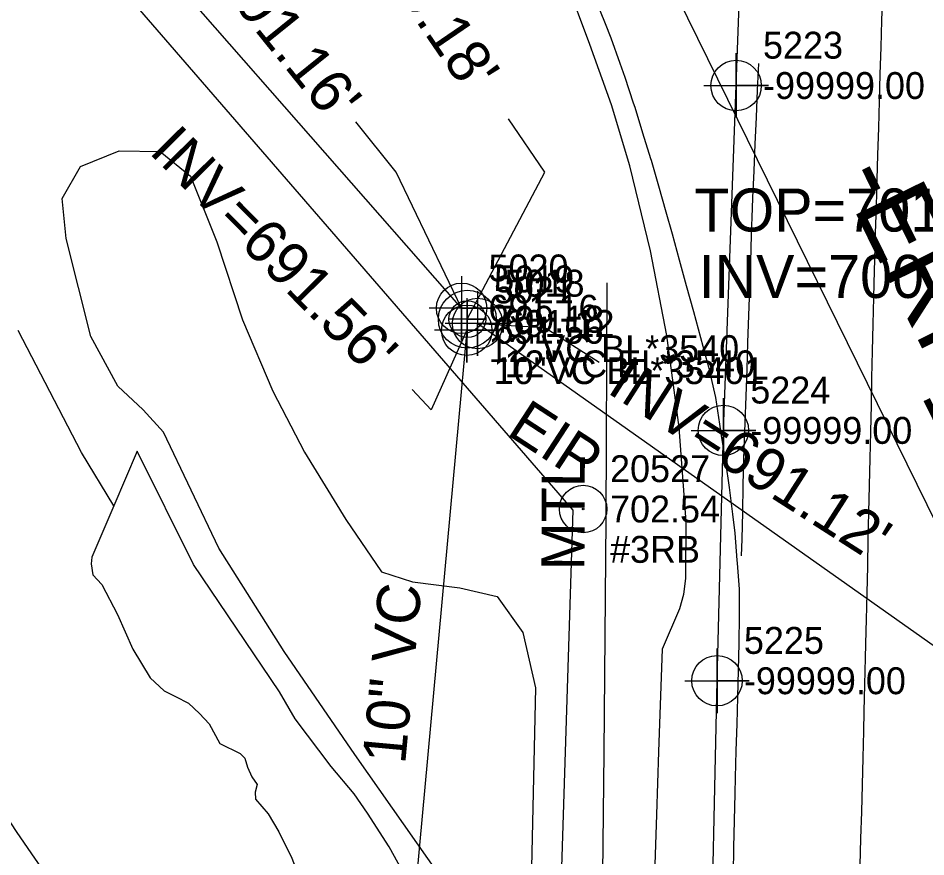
# Model space of a CAD drawing. Extents: x 1516784 to 1522736, y 634838 to 639369.
# Drawn here: x 1520350.8 to 1520435.2, y 637801.1 to 637879 of the extents above; entities that cross this region are included whole.
import ezdxf

# ---------------------------------------------------------------- set-up
doc = ezdxf.new("R2010")
doc.units = 0
for name, color, linetype in [('COGO Default Point Elevation', 7, 'Continuous'), ('COGO Default Point Number', 7, 'Continuous'), ('Exist Environmental Wetland Boundary Cogo Number', 7, 'Continuous'), ('Exist Environmental Wetland Boundary Text', 7, 'Continuous'), ('Exist Guardrail', 7, 'Continuous'), ('Exist Guardrail Text', 7, 'Continuous'), ('Exist Horizontal Alignment Direction Label', 7, 'Continuous'), ('Exist Hydro Stream or Body of Water', 7, 'Continuous'), ('Exist Hydro Stream or Body of Water Text', 7, 'Continuous'), ('Exist Property Iron Pin CELL', 7, 'Continuous'), ('Exist Property Iron Pin Cogo Comment', 7, 'Continuous'), ('Exist Property Iron Pin Cogo Elevation', 7, 'Continuous'), ('Exist Property Iron Pin Cogo Number', 7, 'Continuous'), ('Exist Property Iron Pin Text', 7, 'Continuous'), ('Exist Right of Way Line', 7, 'Continuous'), ('Exist Structure Minor Drop Inlet Top Elevation', 7, 'Continuous'), ('Exist Structure Minor Pipes RCP 18 Inch Invert', 7, 'Continuous'), ('Exist Utilities Gas UG Line SUE LOS B', 7, 'Continuous'), ('Exist Utilities Gas UG Line SUE LOS B Cogo Elevation', 7, 'Continuous'), ('Exist Utilities Gas UG Line SUE LOS B Cogo Number', 7, 'Continuous'), ('Exist Utilities Gas UG Line SUE LOS B Cogo Point CELL', 7, 'Continuous'), ('Exist Utilities Sanitary Sewer Manhole CELL', 7, 'Continuous'), ('Exist Utilities Sanitary Sewer Manhole Cogo Elevation', 7, 'Continuous'), ('Exist Utilities Sanitary Sewer Manhole Cogo Number', 7, 'Continuous'), ('Exist Utilities Sanitary Sewer Manhole Leader', 7, 'Continuous'), ('Exist Utilities Sanitary Sewer Manhole Text', 7, 'Continuous'), ('Exist Utilities Sanitary Sewer UG Line', 7, 'Continuous'), ('Exist Utilities Sanitary Sewer UG Line Cogo Comment', 7, 'Continuous'), ('Exist Utilities Sanitary Sewer UG Line Cogo Elevation', 7, 'Continuous'), ('Exist Utilities Sanitary Sewer UG Line Cogo Number', 7, 'Continuous'), ('Exist Utilities Sanitary Sewer UG Line Cogo Point CELL', 7, 'Continuous'), ('Exist Utilities Sanitary Sewer UG Line Invert Elevation', 7, 'Continuous'), ('Exist Utilities Sanitary Sewer UG Line Leader', 7, 'Continuous'), ('Exist Utilities Sanitary Sewer UG Line Text', 7, 'Continuous'), ('Exist Vegetation Hedge Row', 7, 'Continuous'), ('Scratch_Level_5', 7, 'Continuous')]:
    doc.layers.add(name, color=color, linetype=linetype)

msp = doc.modelspace()

# ---------------------------------------------------------------- linework, layer by layer
at = {"layer": 'COGO Default Point Elevation'}
for points in [[(1520431.184, 637881.303), (1520431.109, 637878.805), (1520431.035, 637876.306), (1520430.961, 637873.808), (1520430.887, 637871.309), (1520430.813, 637868.811), (1520430.739, 637866.312), (1520430.672, 637864.028), (1520430.595, 637861.53), (1520430.519, 637859.031), (1520430.443, 637856.533), (1520430.414, 637855.562), (1520430.357, 637853.063), (1520430.3, 637850.564), (1520430.243, 637848.064), (1520430.186, 637845.565), (1520430.129, 637843.066), (1520430.072, 637840.567), (1520430.015, 637838.068), (1520429.958, 637835.569), (1520429.901, 637833.07), (1520429.844, 637830.571), (1520429.787, 637828.072), (1520429.73, 637825.573), (1520429.673, 637823.074), (1520429.65, 637822.065), (1520429.591, 637819.566), (1520429.533, 637817.067), (1520429.475, 637814.568), (1520429.432, 637812.743), (1520429.364, 637810.244), (1520429.296, 637807.745), (1520429.228, 637805.246), (1520429.16, 637802.747), (1520429.092, 637800.248)], [(1520404.501, 637880.849), (1520405.413, 637878.522), (1520405.941, 637877.176), (1520406.783, 637874.823), (1520407.247, 637873.527), (1520408.033, 637871.154), (1520408.167, 637870.749), (1520408.899, 637868.358), (1520409.63, 637865.968), (1520409.676, 637865.819), (1520410.365, 637863.415), (1520411.055, 637861.012), (1520411.64, 637858.972), (1520412.299, 637856.56), (1520412.959, 637854.149), (1520413.614, 637851.753), (1520414.27, 637849.34), (1520414.926, 637846.928), (1520415.015, 637846.598), (1520415.567, 637844.16), (1520415.658, 637843.755), (1520416.042, 637841.284), (1520416.209, 637840.204), (1520416.59, 637837.733), (1520416.95, 637835.394), (1520417.256, 637832.913), (1520417.476, 637831.129), (1520417.658, 637828.636), (1520417.679, 637828.347), (1520417.875, 637825.949), (1520417.857, 637823.45), (1520417.838, 637820.905), (1520417.772, 637818.406), (1520417.706, 637815.907), (1520417.639, 637813.408), (1520417.573, 637810.91), (1520417.507, 637808.411), (1520417.467, 637806.925), (1520417.412, 637804.426), (1520417.356, 637801.927), (1520417.3, 637799.428)], [(1520419.664, 637874.807), (1520419.556, 637872.31), (1520419.448, 637869.813), (1520419.34, 637867.315), (1520419.233, 637864.818), (1520419.125, 637862.321), (1520419.083, 637861.367), (1520418.998, 637858.869), (1520418.912, 637856.371), (1520418.827, 637853.873), (1520418.741, 637851.375), (1520418.656, 637848.877), (1520418.57, 637846.379), (1520418.484, 637843.88), (1520418.399, 637841.382), (1520418.313, 637838.884), (1520418.286, 637838.083), (1520418.227, 637835.584), (1520418.168, 637833.085), (1520418.109, 637830.586), (1520418.072, 637829.028)]]:
    msp.add_lwpolyline(points, dxfattribs=at)
at = {"layer": 'COGO Default Point Number'}
msp.add_lwpolyline([(1520409.988, 637798.457), (1520410.203, 637804.975), (1520410.391, 637810.804), (1520410.757, 637820.381), (1520412.342, 637824.124), (1520412.722, 637825.48), (1520412.927, 637826.934), (1520412.951, 637832.187), (1520412.3, 637840.957), (1520411.153, 637849.529), (1520409.622, 637857.384), (1520407.698, 637865.279), (1520405.994, 637870.956), (1520403.976, 637876.57), (1520401.805, 637882.501)], dxfattribs=at)
at = {"layer": 'Exist Environmental Wetland Boundary Cogo Number'}
msp.add_lwpolyline([(1520361.047, 637788.842), (1520355.345, 637796.638), (1520350.769, 637803.307), (1520345.377, 637811.482), (1520336.329, 637825.407), (1520331.638, 637833.125), (1520326.352, 637842.523), (1520320.418, 637853.216), (1520316.843, 637859.318), (1520316.247, 637859.778)], dxfattribs=at)
at = {"layer": 'Exist Environmental Wetland Boundary Text'}
msp.add_line((1520409.906, 637885.524), (1520453.231, 637797.305), dxfattribs=at)
at = {"layer": 'Exist Guardrail'}
msp.add_lwpolyline([(1520404.156, 637757.609), (1520405.039, 637785.361), (1520405.323, 637810.742), (1520405.506, 637832.426), (1520405.596, 637854.408)], dxfattribs=at)
at = {"layer": 'Exist Hydro Stream or Body of Water'}
msp.add_lwpolyline([(1520359.729, 637833.671), (1520356.751, 637838.641), (1520350.849, 637849.968)], dxfattribs=at)
at = {"layer": 'Exist Hydro Stream or Body of Water Text'}
for p, q in [((1520361.914, 637838.752), (1520359.729, 637833.671)), ((1520367.135, 637828.24), (1520361.914, 637838.752)), ((1520359.729, 637833.671), (1520357.686, 637828.92)), ((1520375.151, 637816.378), (1520367.135, 637828.24))]:
    msp.add_line(p, q, dxfattribs=at)
for points in [[(1520357.686, 637828.92), (1520357.63, 637828.285), (1520357.783, 637827.28), (1520358.618, 637826.377), (1520360.077, 637823.571)], [(1520360.077, 637823.571), (1520361.506, 637820.352), (1520363.121, 637817.694), (1520364.422, 637816.483), (1520365.462, 637815.957), (1520366.692, 637815.343), (1520367.698, 637814.391), (1520368.602, 637813.425), (1520369.599, 637811.587)], [(1520379.952, 637809.439), (1520376.611, 637813.89), (1520375.151, 637816.378)], [(1520369.599, 637811.587), (1520371.491, 637810.658), (1520371.934, 637810.232), (1520372.162, 637809.379), (1520372.565, 637808.499), (1520373.06, 637807.783), (1520372.871, 637807.065), (1520372.924, 637806.422), (1520374.098, 637805.035)], [(1520386.859, 637799.224), (1520385.34, 637801.982), (1520383.33, 637805.123), (1520382.095, 637806.904), (1520379.952, 637809.439)], [(1520374.098, 637805.035), (1520375.079, 637803.374), (1520376.279, 637800.914), (1520376.856, 637799.477), (1520377.422, 637798.055), (1520378.262, 637796.413), (1520379.186, 637794.88), (1520379.229, 637794.806)]]:
    msp.add_lwpolyline(points, dxfattribs=at)
at = {"layer": 'Exist Property Iron Pin CELL'}
for radius in [2.203, 0.0707]:
    msp.add_circle((1520403.367, 637833.385), radius, dxfattribs=at)
at = {"layer": 'Exist Right of Way Line'}
for p, q in [((1520000.914, 638297.346), (1520402.397, 637833.275)), ((1520402.397, 637833.275), (1520393.319, 637546.213))]:
    msp.add_line(p, q, dxfattribs=at)
at = {"layer": 'Exist Utilities Gas UG Line SUE LOS B'}
msp.add_lwpolyline([(1520401.122, 637354.382), (1520402.422, 637385.791), (1520403.856, 637416.359), (1520404.692, 637446.503), (1520405.047, 637477.267), (1520405.743, 637508.887), (1520406.802, 637539.368), (1520408.241, 637570.499), (1520409.319, 637603.291), (1520409.994, 637633.11), (1520411.515, 637665.368), (1520412.117, 637695.323), (1520413.141, 637725.205), (1520414.219, 637755.916), (1520415.162, 637787.588), (1520415.812, 637817.42), (1520416.407, 637840.693), (1520417.587, 637872.753), (1520418.237, 637890.364), (1520419.072, 637920.653), (1520420.174, 637951.413), (1520420.842, 637982.369), (1520421.988, 638012.853), (1520423.241, 638041.594)], dxfattribs=at)
at = {"layer": 'Exist Utilities Gas UG Line SUE LOS B Cogo Point CELL'}
for points in [[(1520414.587, 637872.753), (1520420.587, 637872.753), (1520417.587, 637872.753), (1520417.587, 637875.753), (1520417.587, 637869.753)], [(1520413.407, 637840.693), (1520419.407, 637840.693), (1520416.407, 637840.693), (1520416.407, 637843.693), (1520416.407, 637837.693)], [(1520412.812, 637817.42), (1520418.812, 637817.42), (1520415.812, 637817.42), (1520415.812, 637820.42), (1520415.812, 637814.42)]]:
    msp.add_lwpolyline(points, dxfattribs=at)
for centre in [(1520417.587, 637872.753), (1520416.407, 637840.693), (1520415.812, 637817.42)]:
    msp.add_circle(centre, 2.344, dxfattribs=at)
at = {"layer": 'Exist Utilities Sanitary Sewer Manhole CELL'}
msp.add_lwpolyline([(1520392.601, 637852.74), (1520392.601, 637849.315), (1520392.601, 637851.028), (1520394.313, 637851.028), (1520390.889, 637851.028)], dxfattribs=at)
for radius in [2.694, 1.712]:
    msp.add_circle((1520392.601, 637851.028), radius, dxfattribs=at)
at = {"layer": 'Exist Utilities Sanitary Sewer Manhole Leader'}
msp.add_lwpolyline([(1520392.601, 637851.028), (1520399.815, 637864.688), (1520396.43, 637869.642)], dxfattribs=at)
at = {"layer": 'Exist Utilities Sanitary Sewer UG Line'}
for p, q in [((1520392.069, 637852.044), (1520196.281, 638075.269)), ((1520529.65, 637754.364), (1520393.555, 637850.627)), ((1520392.551, 637850.001), (1520383.58, 637752.527))]:
    msp.add_line(p, q, dxfattribs=at)
at = {"layer": 'Exist Utilities Sanitary Sewer UG Line Cogo Point CELL'}
for points in [[(1520392.069, 637855.044), (1520392.069, 637849.044), (1520392.069, 637852.044), (1520395.069, 637852.044), (1520389.069, 637852.044)], [(1520393.555, 637853.627), (1520393.555, 637847.627), (1520393.555, 637850.627), (1520396.555, 637850.627), (1520390.555, 637850.627)], [(1520392.551, 637853.001), (1520392.551, 637847.001), (1520392.551, 637850.001), (1520395.551, 637850.001), (1520389.551, 637850.001)]]:
    msp.add_lwpolyline(points, dxfattribs=at)
for centre in [(1520392.069, 637852.044), (1520393.555, 637850.627), (1520392.551, 637850.001)]:
    msp.add_circle(centre, 2.344, dxfattribs=at)
at = {"layer": 'Exist Utilities Sanitary Sewer UG Line Leader'}
for points in [[(1520392.069, 637852.044), (1520385.998, 637864.706), (1520382.233, 637869.378)], [(1520393.555, 637850.627), (1520399.811, 637850.264), (1520404.864, 637847.028)], [(1520392.551, 637850.001), (1520389.253, 637842.615), (1520387.475, 637844.499)]]:
    msp.add_lwpolyline(points, dxfattribs=at)
at = {"layer": 'Exist Vegetation Hedge Row'}
msp.add_lwpolyline([(1520390.159, 637799.137), (1520382.132, 637810.552), (1520375.576, 637820.14), (1520369.503, 637829.739), (1520364.372, 637840.528), (1520362.476, 637842.603), (1520360.119, 637844.815), (1520357.597, 637849.427), (1520355.311, 637858.53), (1520354.949, 637862.25), (1520356.629, 637865.226), (1520360.237, 637866.678), (1520364.061, 637866.622), (1520366.857, 637864.333), (1520369.306, 637858.235), (1520371.715, 637850.962), (1520374.511, 637844.355), (1520377.452, 637838.672), (1520381.308, 637832.421), (1520384.622, 637827.539), (1520387.505, 637826.621), (1520391.915, 637826.058), (1520395.376, 637825.264), (1520397.773, 637821.897), (1520398.936, 637816.769), (1520398.561, 637800.057)], dxfattribs=at)

# ---------------------------------------------------------------- texts
at = {"layer": 'Exist Guardrail Text'}
msp.add_text('MTL', height=4, rotation=89.76554, dxfattribs=at).set_placement((1520403.486, 637827.677))
at = {"layer": 'Exist Horizontal Alignment Direction Label'}
msp.add_text('-ERP_C-', height=7, rotation=296.15583, dxfattribs=at).set_placement((1520427.036, 637864.256))
at = {"layer": 'Exist Property Iron Pin Cogo Comment'}
msp.add_text('#3RB', height=2.5, dxfattribs=at).set_placement((1520405.867, 637828.385))
at = {"layer": 'Exist Property Iron Pin Cogo Elevation'}
msp.add_text('702.54', height=2.5, dxfattribs=at).set_placement((1520405.867, 637832.135))
at = {"layer": 'Exist Property Iron Pin Cogo Number'}
msp.add_text('20527', height=2.5, dxfattribs=at).set_placement((1520405.867, 637835.885))
at = {"layer": 'Exist Property Iron Pin Text'}
msp.add_text('EIP', height=4, rotation=326.89047, dxfattribs=at).set_placement((1520396.147, 637840.369))
at = {"layer": 'Exist Structure Minor Drop Inlet Top Elevation'}
msp.add_text("TOP=701.73'", height=4, dxfattribs=at).set_placement((1520413.701, 637859.179))
at = {"layer": 'Exist Structure Minor Pipes RCP 18 Inch Invert'}
msp.add_text("INV=700.18'", height=4, dxfattribs=at).set_placement((1520414.095, 637853.009))
at = {"layer": 'Exist Utilities Gas UG Line SUE LOS B Cogo Elevation'}
for p in [(1520420.087, 637871.503), (1520418.907, 637839.443), (1520418.312, 637816.17)]:
    msp.add_text('-99999.00', height=2.5, dxfattribs=at).set_placement(p)
at = {"layer": 'Exist Utilities Gas UG Line SUE LOS B Cogo Number'}
for s, p in [('5223', (1520420.087, 637875.253)), ('5224', (1520418.907, 637843.193)), ('5225', (1520418.312, 637819.92))]:
    msp.add_text(s, height=2.5, dxfattribs=at).set_placement(p)
at = {"layer": 'Exist Utilities Sanitary Sewer Manhole Cogo Elevation'}
msp.add_text('709.18', height=2.5, dxfattribs=at).set_placement((1520395.101, 637849.778))
at = {"layer": 'Exist Utilities Sanitary Sewer Manhole Cogo Number'}
msp.add_text('5019', height=2.5, dxfattribs=at).set_placement((1520395.101, 637853.528))
at = {"layer": 'Exist Utilities Sanitary Sewer Manhole Text'}
msp.add_text("TOP=709.18'", height=4, rotation=304.3441, dxfattribs=at).set_placement((1520374.726, 637897.86))
at = {"layer": 'Exist Utilities Sanitary Sewer UG Line Cogo Comment'}
for s, p in [('12"VC BL*3540', (1520394.569, 637847.044)), ('10"VC BL*35401', (1520395.051, 637845.001)), ('12"VC EL*3540', (1520396.055, 637845.627))]:
    msp.add_text(s, height=2.5, dxfattribs=at).set_placement(p)
at = {"layer": 'Exist Utilities Sanitary Sewer UG Line Cogo Elevation'}
for s, p in [('691.16', (1520394.569, 637850.794)), ('691.12', (1520396.055, 637849.377)), ('691.56', (1520395.051, 637848.751))]:
    msp.add_text(s, height=2.5, dxfattribs=at).set_placement(p)
at = {"layer": 'Exist Utilities Sanitary Sewer UG Line Cogo Number'}
for s, p in [('5020', (1520394.569, 637854.544)), ('5018', (1520396.055, 637853.127)), ('5021', (1520395.051, 637852.501))]:
    msp.add_text(s, height=2.5, dxfattribs=at).set_placement(p)
at = {"layer": 'Exist Utilities Sanitary Sewer UG Line Invert Elevation'}
for s, rotation, p in [("INV=691.16'", 308.86055, (1520361.438, 637891.998)), ("INV=691.56'", 314.61515, (1520362.923, 637866.535)), ("INV=691.12'", 327.3585, (1520405.469, 637844.265))]:
    msp.add_text(s, height=4, rotation=rotation, dxfattribs=at).set_placement(p)
at = {"layer": 'Exist Utilities Sanitary Sewer UG Line Text'}
msp.add_text('10" VC', height=4, rotation=84.74161, dxfattribs=at).set_placement((1520386.825, 637809.603))
at = {"layer": 'Scratch_Level_5'}
msp.add_text('COLUMN LOCATION', height=500, rotation=335.03733, dxfattribs=at).set_placement((1516680.966, 637558.941))

doc.saveas('drawing.dxf')
